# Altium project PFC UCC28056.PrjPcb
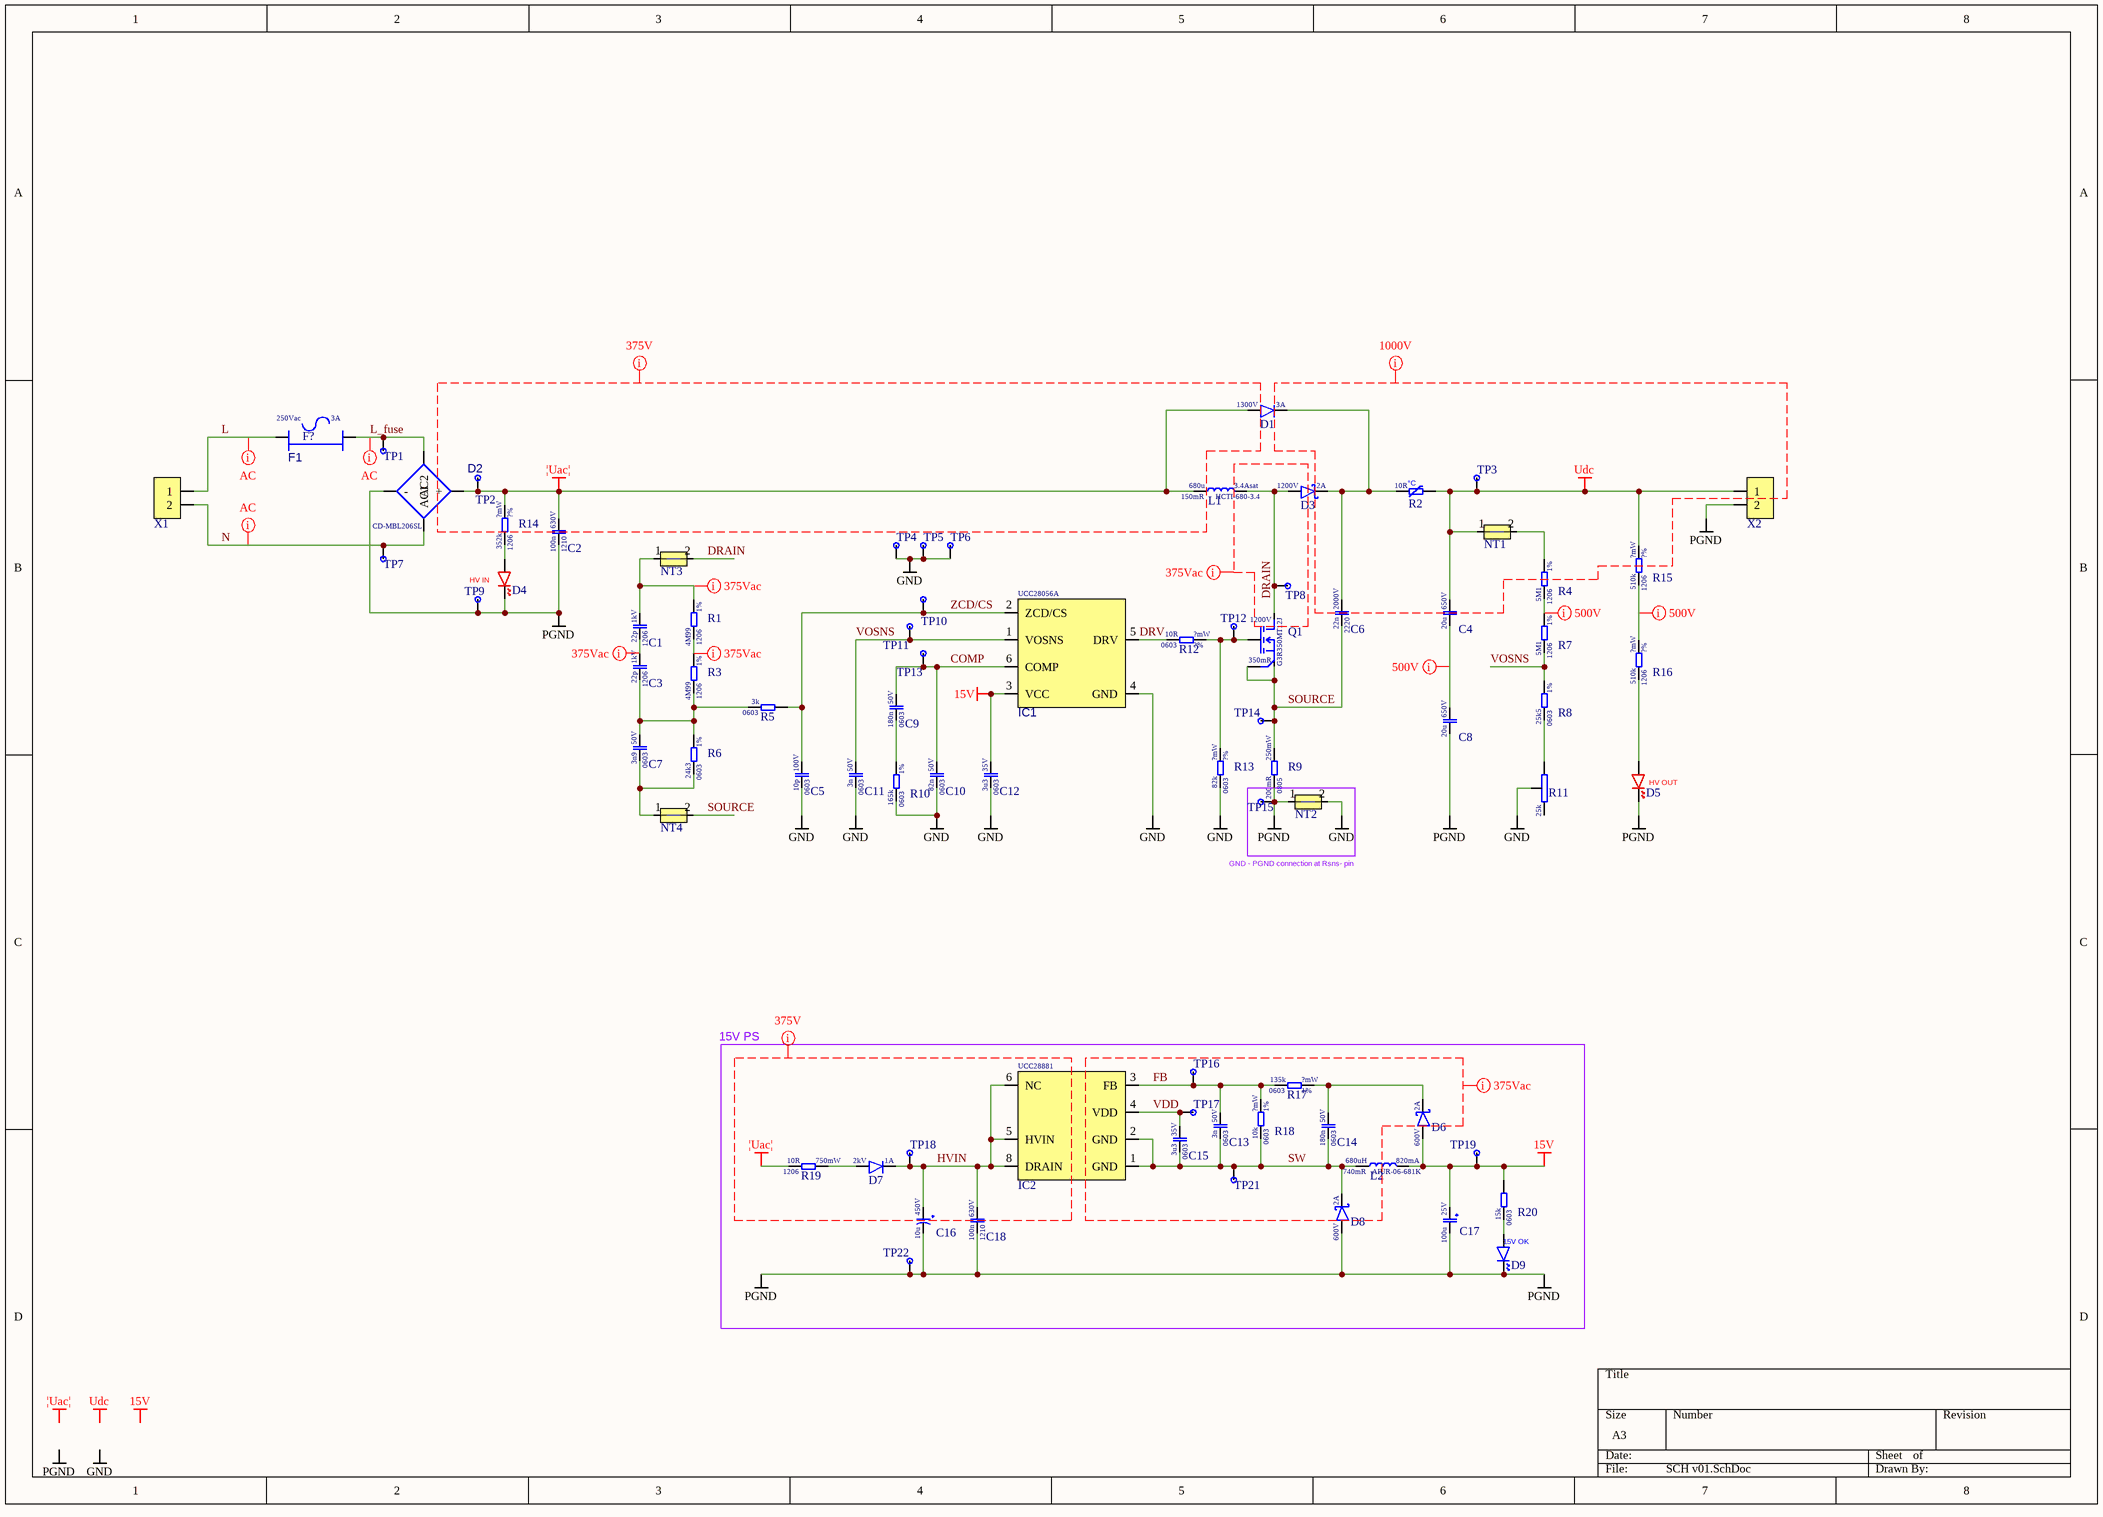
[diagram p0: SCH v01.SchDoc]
1 sheet, 81 parts. Net scope: global (net labels, ports and power ports of the same name join across sheets).
Board file: PCB v01-1.PcbDoc

## Sheet SCH v01.SchDoc
size A3; SheetNumber: 1; SheetTotal: 1

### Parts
C1  Voltage Rating: 1kV  Case Code (Imperial): 1206  Capacitance: 22p  [Cap_1206]  (hidden comment: Generic Capacitor model)
C2  Voltage Rating: 630V  Case Code (Imperial): 1210  Capacitance: 100n  [CAP_1210]  (hidden comment: Generic Capacitor model)
C3  Voltage Rating: 1kV  Case Code (Imperial): 1206  Capacitance: 22p  [Cap_1206]  (hidden comment: Generic Capacitor model)
C4  Voltage Rating: 650V  Capacitance: 20u  [C4AQCBW5200A3FJ]  (hidden comment: Generic Capacitor model)
C5  Voltage Rating: 100V  Case Code (Imperial): 0603  Capacitance: 10p  [CAP 0603]  (hidden comment: Generic Capacitor model)
C6  Voltage Rating: 2000V  Case Code (Imperial): 2220  Capacitance: 22n  [CAP_2220]  (hidden comment: Generic Capacitor model)
C7  Voltage Rating: 50V  Case Code (Imperial): 0603  Capacitance: 3n9  [CAP 0603]  (hidden comment: Generic Capacitor model)
C8  Voltage Rating: 650V  Capacitance: 20u  [C4AQCBW5200A3FJ]  (hidden comment: Generic Capacitor model)
C9  Voltage Rating: 50V  Case Code (Imperial): 0603  Capacitance: 180n  [CAP 0603]  (hidden comment: Generic Capacitor model)
C10  Voltage Rating: 50V  Case Code (Imperial): 0603  Capacitance: 82n  [CAP 0603]  (hidden comment: Generic Capacitor model)
C11  Voltage Rating: 50V  Case Code (Imperial): 0603  Capacitance: 3n  [CAP 0603]  (hidden comment: Generic Capacitor model)
C12  Voltage Rating: 35V  Case Code (Imperial): 0603  Capacitance: 3u3  [CAP 0603]  (hidden comment: Generic Capacitor model)
C13  Voltage Rating: 50V  Case Code (Imperial): 0603  Capacitance: 3n  [CAP 0603]  (hidden comment: Generic Capacitor model)
C14  Voltage Rating: 50V  Case Code (Imperial): 0603  Capacitance: 180n  [CAP 0603]  (hidden comment: Generic Capacitor model)
C15  Voltage Rating: 35V  Case Code (Imperial): 0603  Capacitance: 3u3  [CAP 0603]  (hidden comment: Generic Capacitor model)
C16  Voltage Rating: 450V  Capacitance: 10u  [ELKO 10x20mm]  (hidden comment: Cap_Polarized)
C17  Voltage Rating: 25V  Capacitance: 100u  [CAP_TANTAL_2917]  (hidden comment: Cap_Tantal)
C18  Voltage Rating: 630V  Case Code (Imperial): 1210  Capacitance: 100n  [CAP_1210]  (hidden comment: Generic Capacitor model)
D1  Forward Current: 3A  Reverse Voltage: 1300V  [DO-201AD]  (hidden comment: Diode)
D2  CD-MBL206SL  [CD-MBL206SL]
D3  Forward Current: 2A  Reverse Voltage: 1200V  [TO252-2_DPAK_B]  (hidden comment: Diode Schottky)
D4  Diode LED Red  [DIODE_0603]  (value not drawn)
D5  Diode LED Red  [DIODE_0603]  (value not drawn)
D6  Forward Current: 2A  Reverse Voltage: 600V  [SMAF]  (hidden comment: Diode Schottky)
D7  Forward Current: 1A  Reverse Voltage: 2kV  [SOD-123FL]  (hidden comment: Diode)
D8  Forward Current: 2A  Reverse Voltage: 600V  [SMAF]  (hidden comment: Diode Schottky)
D9  Diode LED Blue  [DIODE_0603]  (value not drawn)
F1  64600001003  [64600001003]  (value not drawn)
F?  Voltage: 250Vac  Hold Current: 3A  (hidden comment: Fuse no FP)  (graphical)
IC1  UCC28056A  [SOT-23-6]
IC2  UCC28881  [SOIC-7]
L1  Resistance: 150mR  Saturation current: 3.4Asat  Inductance: 680u  [HCTI-680-3.4]  (hidden comment: HCTI-680-3.4)
L2  Resistance: 740mR  Saturation current: 820mA  Inductance: 680uH  [AIUR-06-681K]  (hidden comment: AIUR-06-681K)
NT1  NT  [NETTIE_0.3MM]  (value not drawn)  (net tie, no BOM)
NT2  NT  [NETTIE_0.5MM]  (value not drawn)  (net tie, no BOM)
NT3  NT  [NETTIE_0.3MM]  (value not drawn)  (net tie, no BOM)
NT4  NT  [NETTIE_0.3MM]  (value not drawn)  (net tie, no BOM)
Q1  Manufacturer Part Number: G3R350MT12J  Rds: 350mR  Voltage: 1200V  [TO-263-7 D2PAK]  (hidden comment: Nmos_KS)
R1  Resistance Tolerance: 1%  Resistance: 4M99  Case Code (Imperial): 1206  [RES_1206]  (hidden comment: Generic resistor model)
R2  Resistance: 10R  [ICL101D05MIB]  (hidden comment: NTC 10R 1A)
R3  Resistance Tolerance: 1%  Resistance: 4M99  Case Code (Imperial): 1206  [RES_1206]  (hidden comment: Generic resistor model)
R4  Resistance Tolerance: 1%  Resistance: 5M1  Case Code (Imperial): 1206  [RES_1206]  (hidden comment: Generic resistor model)
R5  Resistance: 3k  Case Code (Imperial): 0603  [RES_0603]  (hidden comment: Generic resistor model)
R6  Resistance Tolerance: 1%  Resistance: 24k3  Case Code (Imperial): 0603  [RES_0603]  (hidden comment: Generic resistor model)
R7  Resistance Tolerance: 1%  Resistance: 5M1  Case Code (Imperial): 1206  [RES_1206]  (hidden comment: Generic resistor model)
R8  Resistance Tolerance: 1%  Resistance: 25k5  Case Code (Imperial): 0603  [RES_0603]  (hidden comment: Generic resistor model)
R9  Resistance: 200mR  Power Rating: 250mW  Case Code (Imperial): 0805  [Res_0805]  (hidden comment: Generic resistor model)
R10  Resistance Tolerance: 1%  Resistance: 165k  Case Code (Imperial): 0603  [RES_0603]  (hidden comment: Generic resistor model)
R11  Resistance: 25k  [RES-67WR10KLF]  (hidden comment: 67WR25KLF)
R12  Resistance Tolerance: ?%  Resistance: 10R  Power Rating: ?mW  Case Code (Imperial): 0603  [RES_0603]  (hidden comment: Generic resistor model)
R13  Resistance Tolerance: ?%  Resistance: 82k  Power Rating: ?mW  Case Code (Imperial): 0603  [RES_0603]  (hidden comment: Generic resistor model)
R14  Resistance Tolerance: ?%  Resistance: 352k  Power Rating: ?mW  Case Code (Imperial): 1206  [RES_1206]  (hidden comment: Generic resistor model)
R15  Resistance Tolerance: ?%  Resistance: 510k  Power Rating: ?mW  Case Code (Imperial): 1206  [RES_1206]  (hidden comment: Generic resistor model)
R16  Resistance Tolerance: ?%  Resistance: 510k  Power Rating: ?mW  Case Code (Imperial): 1206  [RES_1206]  (hidden comment: Generic resistor model)
R17  Resistance Tolerance: 1%  Resistance: 135k  Power Rating: ?mW  Case Code (Imperial): 0603  [RES_0603]  (hidden comment: Generic resistor model)
R18  Resistance Tolerance: 1%  Resistance: 10k  Power Rating: ?mW  Case Code (Imperial): 0603  [RES_0603]  (hidden comment: Generic resistor model)
R19  Resistance: 10R  Power Rating: 750mW  Case Code (Imperial): 1206  [RES_1206]  (hidden comment: Generic resistor model)
R20  Resistance: 15k  Case Code (Imperial): 0603  [RES_0603]  (hidden comment: Generic resistor model)
TP1  Test Point  [TEST_POINT_THT]  (value not drawn)  (no BOM)
TP2  Test Point  [TEST_POINT_THT]  (value not drawn)  (no BOM)
TP3  Test Point  [TEST_POINT_THT]  (value not drawn)  (no BOM)
TP4  Test Point  [TEST_POINT_THT]  (value not drawn)  (no BOM)
TP5  Test Point  [TEST_POINT_THT]  (value not drawn)  (no BOM)
TP6  Test Point  [TEST_POINT_THT]  (value not drawn)  (no BOM)
TP7  Test Point  [TEST_POINT_THT]  (value not drawn)  (no BOM)
TP8  Test Point  [TEST_POINT_THT]  (value not drawn)  (no BOM)
TP9  Test Point  [TEST_POINT_THT]  (value not drawn)  (no BOM)
TP10  Test Point  [TEST_POINT_THT]  (value not drawn)  (no BOM)
TP11  Test Point  [TEST_POINT_THT]  (value not drawn)  (no BOM)
TP12  Test Point  [TEST_POINT_THT]  (value not drawn)  (no BOM)
TP13  Test Point  [TEST_POINT_THT]  (value not drawn)  (no BOM)
TP14  Test Point  [TEST_POINT_THT]  (value not drawn)  (no BOM)
TP15  Test Point  [TEST_POINT_THT]  (value not drawn)  (no BOM)
TP16  Test Point  [TEST_POINT_THT]  (value not drawn)  (no BOM)
TP17  Test Point  [TEST_POINT_THT]  (value not drawn)  (no BOM)
TP18  Test Point  [TEST_POINT_THT]  (value not drawn)  (no BOM)
TP19  Test Point  [TEST_POINT_THT]  (value not drawn)  (no BOM)
TP21  Test Point  [TEST_POINT_THT]  (value not drawn)  (no BOM)
TP22  Test Point  [TEST_POINT_THT]  (value not drawn)  (no BOM)
X1  Screw Terminal 2pos  [Screw terminal 2pos 5.08mm]  (value not drawn)
X2  Screw Terminal 2pos  [Screw terminal 2pos 5.08mm]  (value not drawn)

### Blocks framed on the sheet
15V PS: C13-C18 D6-D9 IC2 L2 R17-R20 TP16-TP19 TP21 TP22

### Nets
15V: C12.2 C17.+ D6.A IC1.3(VCC) L2.2 R20.2 TP19.1
GND: C5.1 C10.1 C11.1 C12.1 IC1.4(GND) NT2.2 R10.1 R11.2 R13.1 TP4.1 TP5.1 TP6.1
PGND: C2.1 C8.1 C16.- C17.- C18.1 D2.- D4.K D5.K D8.A D9.K NT2.1 R9.1 TP9.1 TP15.1 TP22.1 X2.2
Udc: C4.2 NT1.1 R2.2 R15.2 TP3.1 X2.1
¦Uac¦: C2.2 D1.A D2.+ L1.1 R14.2 R19.1 TP2.1
COMP: C9.2 C10.2 IC1.6(COMP) TP13.1
DRAIN: D3.A L1.2 NT3.2 Q1.D TP8.1
DRV: IC1.5(DRV) R12.1
FB: C13.2 IC2.3(FB) R17.1 R18.2 TP16.1
HVIN: C16.+ C18.2 D7.K IC2.5(HVIN) IC2.6(NC) IC2.8(DRAIN) TP18.1
L: F1.1 X1.1
L_fuse: D2.AC2 F1.2 TP1.1
N: D2.AC1 TP7.1 X1.2
SOURCE: C6.1 NT4.2 Q1.KS Q1.S R9.2 TP14.1
SW: C13.1 C14.1 C15.1 D8.K IC2.1(GND) IC2.2(GND) L2.1 R18.1 TP21.1
VDD: C15.2 IC2.4(VDD) TP17.1
VOSNS: C11.2 IC1.1(VOSNS) R7.1 R8.2 TP11.1
ZCD/CS: C5.2 IC1.2(ZCD/CS) R5.2 TP10.1
NetC1_1: C1.1 C3.2
NetC1_2: C1.2 NT3.1 R1.2
NetC3_1: C3.1 C7.2 R3.1 R5.1 R6.2
NetC4_1: C4.1 C8.2
NetC6_2: C6.2 D1.K D3.K R2.1
NetC7_1: C7.1 NT4.1 R6.1
NetC9_1: C9.1 R10.2
NetC14_2: C14.2 D6.K R17.2
NetD4_A: D4.A R14.1
NetD5_A: D5.A R16.1
NetD7_A: D7.A R19.2
NetD9_A: D9.A R20.1
NetNT1_2: NT1.2 R4.2
NetQ1_G: Q1.G R12.2 R13.2 TP12.1
NetR1_1: R1.1 R3.2
NetR4_1: R4.1 R7.2
NetR8_1: R8.1 R11.3
NetR15_1: R15.1 R16.2

Not connected (* = marked no-connect by the designer): R11 1

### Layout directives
net class 375V: HVIN, ¦Uac¦
net class 375Vac: DRAIN, FB, NetC1_1, NetC1_2, NetR1_1, SW, VDD
net class 1000V: DRAIN, PGND, Udc
net class AC: L, L_fuse, N
net class 500V: NetC4_1, NetR4_1, NetR15_1

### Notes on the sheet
- HV IN
- (near D5) HV OUT
- GND - PGND connection at Rsns- pin
- (near D9) 15V OK
- Labels drawn without touching a wire or pin: 15V, GND, PGND, Udc, ¦Uac¦

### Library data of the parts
C1 C3 = Cap: Manufacturer: Walsin; Manufacturer Part Number: 1206N220J102CT
C2 C18 = Cap: Manufacturer: Kemet; Manufacturer Part Number: C1210C104KBRACAUTO
C4 C8 = Cap: Manufacturer: Kemet
C5 = Cap: Manufacturer: Kemet; Manufacturer Part Number: C0603C100J1GAC
C6 = Cap: Manufacturer: Kyocera; Manufacturer Part Number: 2220GC223KAT2A
C7 = Cap: Manufacturer: Vishay; Manufacturer Part Number: VJ0603Y392KXACW1BC
C9 C14 = Cap: Manufacturer: Murata; Manufacturer Part Number: GCJ188R91H184KA01D
C10 = Cap: Manufacturer: Murata; Manufacturer Part Number: GCM188L81H823KA57D
C11 C13 = Cap: Manufacturer: Murata; Manufacturer Part Number: GRM1885C1H302JA01D
C12 C15 = Cap: Manufacturer: TDK; Manufacturer Part Number: C1608X5R1V335M080AC
C16 = Cap_Polarized: Generic polarized cap symbol; Manufacturer: Panasonic; Manufacturer Part Number: EEU-EE2W100U
C17 = Cap_Tantal: Generic tantal cap symbol; Manufacturer: Kemet; Manufacturer Part Number: T491X107M025AT
D1 = Diode: General Diode symbol; Manufacturer: Vishay; Manufacturer Part Number: BY255P-E3/73
D2 = CD-MBL206SL: Diode Bridge 600V 2A; Manufacturer: Bourns
D3 = Diode Schottky: General Schottky Diode symbol; Manufacturer: Infineon; Manufacturer Part Number: IDM02G120C5XTMA1
D4 D5 = Diode LED Red: Generic red LED symbol; Manufacturer: Wurth; Manufacturer Part Number: 150060RS75000
D6 D8 = Diode Schottky: General Schottky Diode symbol; Manufacturer: Comchip; Manufacturer Part Number: AES2JF-HF
D7 = Diode: General Diode symbol; Manufacturer: MCC; Manufacturer Part Number: GS1Z-LTP
D9 = Diode LED Blue: Generic blue LED symbol; Manufacturer: Wurth; Manufacturer Part Number: 150060BS75000
F1 = 64600001003: Fuse Holder 5X20MM 250V 6.3A; Manufacturer: Littlefuse
F? = Fuse no FP: Generic fuse symbol - no FP; Manufacturer: Littlefuse; Manufacturer Part Number: 06173.15MXP
IC1 = UCC28056A: PFC TM IC; Manufacturer: Texas Instruments
IC2 = UCC28881: 700-V Lowest Quiescent current off-line switcher; Manufacturer: Texas Instruments
L1 = HCTI-680-3.4: Inductor THT 680uH 3.4A 150mR; Manufacturer: Bel Signal Transformer
L2 = AIUR-06-681K: Power Inductor THT 680uH 820mA 740mR; Manufacturer: Abracon
NT1-NT4 = NetTie: Net Tie
Q1 = Nmos_KS: Generic Nmos symbol with Kelvin Source; Manufacturer: GeneSiC
R1 R3 = Res: Manufacturer: ROHM; Manufacturer Part Number: KTR18EZPF4994
R2 = ICL101D05MIB: NTC 10R 1A 5mm THT; Manufacturer: Eaton
R4 R7 = Res: Manufacturer: ROHM; Manufacturer Part Number: KTR18EZPF5104
R5 = Res: Manufacturer: Yageo; Manufacturer Part Number: AC0603JR-073KL
R6 = Res: Manufacturer: Vishay; Manufacturer Part Number: CRCW060324K3FKEB
R8 = Res: Manufacturer: Yageo; Manufacturer Part Number: RT0603DRE0725K5L
R9 = Res: Manufacturer: Eaton; Manufacturer Part Number: MFLA0805R2000FA
R10 = Res: Manufacturer: Panasonic; Manufacturer Part Number: ERJ-3EKF1653V
R11 = 67WR25KLF: Trimpot, 25 kohm, Through Hole, 20 Turns, Multi Turn, Cermet, Top Adjust,; Manufacturer: BI Technologies
R12 = Res: Manufacturer: Walsin; Manufacturer Part Number: WR06X10R0FTL
R13 = Res: Manufacturer: Bourns; Manufacturer Part Number: CR0603-JW-823ELF
R14 = Res: Manufacturer: KOA; Manufacturer Part Number: RN73H2BTTD3523F100
R15 R16 = Res: Manufacturer: Yageo; Manufacturer Part Number: RT1206FRE07510KL
R17 = Res: Manufacturer: Yageo; Manufacturer Part Number: RT0603BRD07135KL
R18 = Res: Manufacturer: TE; Manufacturer Part Number: CRG0603F10K/10
R19 = Res: Manufacturer: Koa; Manufacturer Part Number: SG73P2BTTD100J
R20 = Res: Manufacturer: Kamaya; Manufacturer Part Number: RMC1/16K1502FTP
X1 X2 = Screw Terminal 2pos: Screw terminal 2 pos, pith 5.08mm; Manufacturer: Weidmuller; Manufacturer Part Number: 1760510000; Connector Type: PCB,Terminal Block; Current: 15A; Current Rating: 16A; Max Supply Voltage: 300V; Number of Circuits: 2; Number of Levels: 1; Wire Gauge (Max): 26AWG; Wire Gauge (Min): 14AWG; Wire/Cable Gauge: 24AWG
